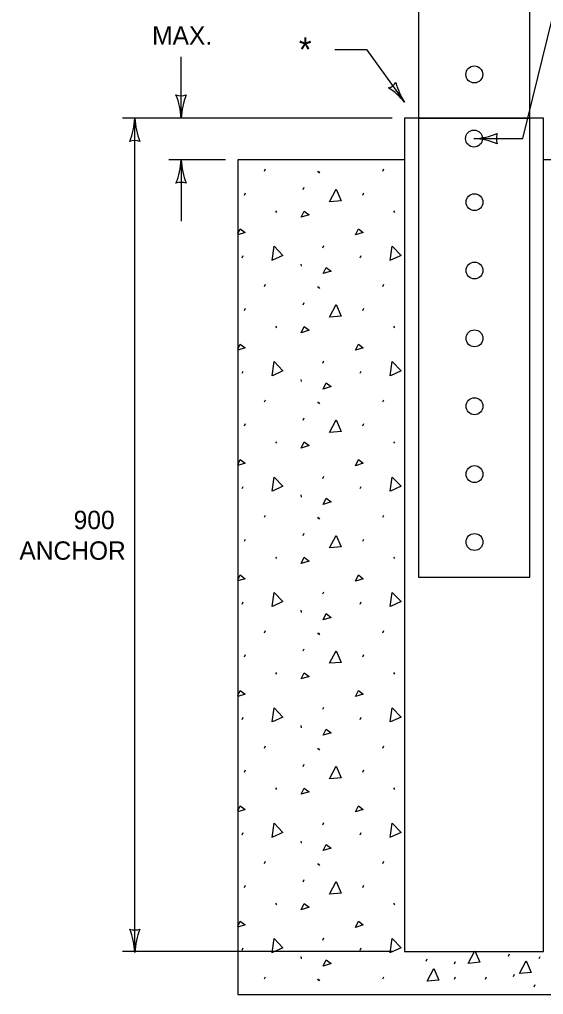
# Model space of a CAD drawing. Extents: x 49940 to 50043, y 49986 to 50011.
# Drawn here: x 50038.243 to 50039.957, y 49990.668 to 49993.853 of the extents above; entities that cross this region are included whole.
import ezdxf

# ---------------------------------------------------------------- set-up
doc = ezdxf.new("R2010")
doc.units = 0
for name, color, linetype in [('Level 1', 7, 'Continuous'), ('Level 2', 7, 'Continuous'), ('Level 3', 7, 'Continuous'), ('Level 4', 7, 'Continuous')]:
    doc.layers.add(name, color=color, linetype=linetype)

msp = doc.modelspace()

# ---------------------------------------------------------------- linework, layer by layer
at = {"layer": 'Level 1'}
for p, q in [((50039.9566, 49993.5307), (50039.5022, 49993.5307)), ((50039.5022, 49993.5307), (50039.5022, 49990.8091)), ((50039.9566, 49990.8091), (50039.9566, 49993.5307)), ((50039.5022, 49993.3944), (50038.9568, 49993.3944)), ((50038.9568, 49993.3944), (50038.9568, 49990.6682)), ((50040.5018, 49993.3944), (50039.9566, 49993.3944)), ((50039.0446, 49993.358), (50039.0478, 49993.3652)), ((50039.2181, 49993.358), (50039.2214, 49993.353)), ((50039.2214, 49993.3561), (50039.2247, 49993.3513)), ((50039.4311, 49993.358), (50039.4344, 49993.3652)), ((50038.9792, 49993.2795), (50038.9823, 49993.2868)), ((50039.1704, 49993.2981), (50039.1736, 49993.3054)), ((50039.3658, 49993.2795), (50039.369, 49993.2868)), ((50039.08, 49993.228), (50039.0833, 49993.2231)), ((50039.4666, 49993.228), (50039.4698, 49993.2231)), ((50039.235, 49993.1076), (50039.2383, 49993.115)), ((50038.9712, 49993.0745), (50038.9744, 49993.0819)), ((50039.3577, 49993.0745), (50039.3608, 49993.0819)), ((50039.163, 49993.0543), (50039.1638, 49993.0469)), ((50039.0446, 49992.981), (50039.0478, 49992.9883)), ((50039.2181, 49992.981), (50039.2214, 49992.9761)), ((50039.2214, 49992.979), (50039.2247, 49992.9743)), ((50039.4311, 49992.981), (50039.4344, 49992.9883)), ((50038.9792, 49992.9027), (50038.9823, 49992.9099)), ((50039.1704, 49992.9212), (50039.1736, 49992.9285)), ((50039.3658, 49992.9027), (50039.369, 49992.9099)), ((50039.08, 49992.851), (50039.0833, 49992.8461)), ((50039.4666, 49992.851), (50039.4698, 49992.8461)), ((50039.235, 49992.7307), (50039.2383, 49992.738)), ((50038.9712, 49992.6976), (50038.9744, 49992.7048)), ((50039.163, 49992.6774), (50039.1638, 49992.6701)), ((50039.3577, 49992.6976), (50039.3608, 49992.7048)), ((50039.0446, 49992.604), (50039.0478, 49992.6112)), ((50039.4311, 49992.604), (50039.4344, 49992.6112)), ((50039.2181, 49992.604), (50039.2214, 49992.5993)), ((50039.2214, 49992.6022), (50039.2247, 49992.5973)), ((50039.1704, 49992.5442), (50039.1736, 49992.5515)), ((50038.9792, 49992.5257), (50038.9823, 49992.5329)), ((50039.3658, 49992.5257), (50039.369, 49992.5329)), ((50039.08, 49992.474), (50039.0833, 49992.469)), ((50039.4666, 49992.474), (50039.4698, 49992.469)), ((50039.235, 49992.3538), (50039.2383, 49992.361)), ((50038.9712, 49992.3206), (50038.9744, 49992.3279)), ((50039.3577, 49992.3206), (50039.3608, 49992.3279)), ((50039.163, 49992.3003), (50039.1638, 49992.2932)), ((50039.0446, 49992.2271), (50039.0478, 49992.2343)), ((50039.4311, 49992.2271), (50039.4344, 49992.2343)), ((50039.2181, 49992.2271), (50039.2214, 49992.2223)), ((50039.2214, 49992.2252), (50039.2247, 49992.2204)), ((50039.1704, 49992.1672), (50039.1736, 49992.1746)), ((50038.9792, 49992.1487), (50038.9823, 49992.1559)), ((50039.3658, 49992.1487), (50039.369, 49992.1559)), ((50039.08, 49992.0971), (50039.0833, 49992.0921)), ((50039.4666, 49992.0971), (50039.4698, 49992.0921)), ((50039.235, 49991.9767), (50039.2383, 49991.984)), ((50038.9712, 49991.9437), (50038.9744, 49991.9509)), ((50039.3577, 49991.9437), (50039.3608, 49991.9509)), ((50039.163, 49991.9233), (50039.1638, 49991.9162)), ((50039.0446, 49991.85), (50039.0478, 49991.8573)), ((50039.2181, 49991.85), (50039.2214, 49991.8452)), ((50039.2214, 49991.8482), (50039.2247, 49991.8434)), ((50039.4311, 49991.85), (50039.4344, 49991.8573)), ((50039.1704, 49991.7903), (50039.1736, 49991.7976)), ((50038.9792, 49991.7717), (50038.9823, 49991.779)), ((50039.3658, 49991.7717), (50039.369, 49991.779)), ((50039.08, 49991.72), (50039.0833, 49991.7151)), ((50039.4666, 49991.72), (50039.4698, 49991.7151)), ((50039.235, 49991.5998), (50039.2383, 49991.607)), ((50038.9712, 49991.5668), (50038.9744, 49991.574)), ((50039.3577, 49991.5668), (50039.3608, 49991.574)), ((50039.163, 49991.5466), (50039.1638, 49991.5392)), ((50039.0446, 49991.4731), (50039.0478, 49991.4804)), ((50039.2181, 49991.4731), (50039.2214, 49991.4683)), ((50039.2214, 49991.4712), (50039.2247, 49991.4664)), ((50039.4311, 49991.4731), (50039.4344, 49991.4804)), ((50038.9792, 49991.3947), (50038.9823, 49991.4019)), ((50039.1704, 49991.4133), (50039.1736, 49991.4206)), ((50039.3658, 49991.3947), (50039.369, 49991.4019)), ((50039.08, 49991.3431), (50039.0833, 49991.3383)), ((50039.4666, 49991.3431), (50039.4698, 49991.3383)), ((50039.235, 49991.2229), (50039.2383, 49991.2301)), ((50038.9712, 49991.1897), (50038.9744, 49991.1969)), ((50039.3577, 49991.1897), (50039.3608, 49991.1969)), ((50039.163, 49991.1694), (50039.1638, 49991.1622)), ((50039.0446, 49991.0961), (50039.0478, 49991.1034)), ((50039.2181, 49991.0961), (50039.2214, 49991.0913)), ((50039.2214, 49991.0943), (50039.2247, 49991.0894)), ((50039.4311, 49991.0961), (50039.4344, 49991.1034)), ((50038.9792, 49991.0177), (50038.9823, 49991.0251)), ((50039.1704, 49991.0362), (50039.1736, 49991.0437)), ((50039.3658, 49991.0177), (50039.369, 49991.0251)), ((50039.08, 49990.9661), (50039.0833, 49990.9613)), ((50039.4666, 49990.9661), (50039.4698, 49990.9613)), ((50039.235, 49990.8458), (50039.2383, 49990.853)), ((50038.9712, 49990.8128), (50038.9744, 49990.8201)), ((50039.3577, 49990.8128), (50039.3608, 49990.8201)), ((50039.5022, 49990.8091), (50039.9566, 49990.8091)), ((50039.8423, 49990.7936), (50039.8456, 49990.8009)), ((50039.163, 49990.7925), (50039.1638, 49990.7852)), ((50039.5735, 49990.777), (50039.5768, 49990.7842)), ((50039.666, 49990.7687), (50039.6692, 49990.7759)), ((50039.9431, 49990.7853), (50039.9463, 49990.7926)), ((50039.8591, 49990.7266), (50039.8623, 49990.7341)), ((50039.0446, 49990.7191), (50039.0478, 49990.7264)), ((50039.2181, 49990.7191), (50039.2214, 49990.7143)), ((50039.2214, 49990.7174), (50039.2247, 49990.7125)), ((50039.4311, 49990.7191), (50039.4344, 49990.7264)), ((50039.666, 49990.7183), (50039.6692, 49990.7257)), ((50039.7668, 49990.7183), (50039.7699, 49990.7257)), ((50039.9262, 49990.6934), (50039.9296, 49990.7006)), ((50038.9568, 49990.6682), (50040.5018, 49990.6682))]:
    msp.add_line(p, q, dxfattribs=at)
for points in [[(50039.5482, 49994.4155), (50039.5482, 49993.5309), (50039.9116, 49993.5309), (50039.9114, 49994.4156)], [(50039.2568, 49993.2578), (50039.2786, 49993.2989), (50039.2955, 49993.261), (50039.2576, 49993.2578)], [(50039.1648, 49993.207), (50039.1746, 49993.2271), (50039.1908, 49993.2151), (50039.1648, 49993.207)], [(50038.9568, 49993.1528), (50038.9649, 49993.1694), (50038.981, 49993.1574), (50038.9568, 49993.1497)], [(50039.3419, 49993.1492), (50039.3515, 49993.1694), (50039.3675, 49993.1574), (50039.3419, 49993.1492)], [(50039.0692, 49993.0661), (50039.0757, 49993.1123), (50039.1046, 49993.0826), (50039.0702, 49993.0666)], [(50039.4559, 49993.0661), (50039.4624, 49993.1123), (50039.4913, 49993.0826), (50039.4567, 49993.0666)], [(50039.2366, 49993.0228), (50039.2464, 49993.0432), (50039.2626, 49993.031), (50039.2366, 49993.0228)], [(50039.2568, 49992.8808), (50039.2786, 49992.9219), (50039.2955, 49992.884), (50039.2576, 49992.8808)], [(50039.1648, 49992.83), (50039.1746, 49992.85), (50039.1908, 49992.8381), (50039.1648, 49992.83)], [(50038.9568, 49992.7758), (50038.9649, 49992.7925), (50038.981, 49992.7804), (50038.9568, 49992.7728)], [(50039.3419, 49992.7724), (50039.3515, 49992.7925), (50039.3675, 49992.7804), (50039.3419, 49992.7724)], [(50039.0692, 49992.6893), (50039.0757, 49992.7354), (50039.1046, 49992.7056), (50039.0702, 49992.6896)], [(50039.4559, 49992.6893), (50039.4624, 49992.7354), (50039.4913, 49992.7056), (50039.4567, 49992.6896)], [(50039.2366, 49992.646), (50039.2464, 49992.6661), (50039.2626, 49992.6541), (50039.2366, 49992.646)], [(50039.2568, 49992.5038), (50039.2786, 49992.545), (50039.2955, 49992.5071), (50039.2576, 49992.5038)], [(50039.1648, 49992.4529), (50039.1746, 49992.4732), (50039.1908, 49992.4611), (50039.1648, 49992.4529)], [(50038.9568, 49992.3987), (50038.9649, 49992.4155), (50038.981, 49992.4034), (50038.9568, 49992.3957)], [(50039.3419, 49992.3952), (50039.3515, 49992.4155), (50039.3675, 49992.4034), (50039.3419, 49992.3952)], [(50039.0692, 49992.3124), (50039.0757, 49992.3584), (50039.1046, 49992.3286), (50039.0702, 49992.3125)], [(50039.4559, 49992.3124), (50039.4624, 49992.3584), (50039.4913, 49992.3286), (50039.4567, 49992.3125)], [(50039.2366, 49992.269), (50039.2464, 49992.2891), (50039.2626, 49992.2772), (50039.2366, 49992.269)], [(50039.2568, 49992.127), (50039.2786, 49992.168), (50039.2955, 49992.1302), (50039.2576, 49992.127)], [(50039.1648, 49992.076), (50039.1746, 49992.0963), (50039.1908, 49992.084), (50039.1648, 49992.076)], [(50038.9568, 49992.0218), (50038.9649, 49992.0385), (50038.981, 49992.0264), (50038.9568, 49992.019)], [(50039.3419, 49992.0183), (50039.3515, 49992.0385), (50039.3675, 49992.0264), (50039.3419, 49992.0183)], [(50039.0692, 49991.9353), (50039.0757, 49991.9815), (50039.1046, 49991.9517), (50039.0702, 49991.9356)], [(50039.4559, 49991.9353), (50039.4624, 49991.9815), (50039.4913, 49991.9517), (50039.4567, 49991.9356)], [(50039.2366, 49991.8921), (50039.2464, 49991.9122), (50039.2626, 49991.9001), (50039.2366, 49991.8921)], [(50039.2568, 49991.75), (50039.2786, 49991.791), (50039.2955, 49991.7532), (50039.2576, 49991.75)], [(50039.1648, 49991.6991), (50039.1746, 49991.7193), (50039.1908, 49991.7071), (50039.1648, 49991.6991)], [(50038.9568, 49991.6448), (50038.9649, 49991.6616), (50038.981, 49991.6495), (50038.9568, 49991.642)], [(50039.3419, 49991.6414), (50039.3515, 49991.6616), (50039.3675, 49991.6495), (50039.3419, 49991.6414)], [(50039.0692, 49991.5584), (50039.0757, 49991.6046), (50039.1046, 49991.5746), (50039.0702, 49991.5587)], [(50039.4559, 49991.5584), (50039.4624, 49991.6046), (50039.4913, 49991.5746), (50039.4567, 49991.5587)], [(50039.2366, 49991.515), (50039.2464, 49991.5352), (50039.2626, 49991.5231), (50039.2366, 49991.515)], [(50039.2568, 49991.3728), (50039.2786, 49991.4141), (50039.2955, 49991.3761), (50039.2576, 49991.3728)], [(50039.1648, 49991.3221), (50039.1746, 49991.3422), (50039.1908, 49991.3302), (50039.1648, 49991.3221)], [(50038.9568, 49991.2679), (50038.9649, 49991.2846), (50038.981, 49991.2724), (50038.9568, 49991.2648)], [(50039.3419, 49991.2644), (50039.3515, 49991.2846), (50039.3675, 49991.2724), (50039.3419, 49991.2644)], [(50039.0692, 49991.1813), (50039.0757, 49991.2274), (50039.1046, 49991.1976), (50039.0702, 49991.1817)], [(50039.4559, 49991.1813), (50039.4624, 49991.2274), (50039.4913, 49991.1976), (50039.4567, 49991.1817)], [(50039.2366, 49991.1381), (50039.2464, 49991.1583), (50039.2626, 49991.1462), (50039.2366, 49991.1381)], [(50039.2568, 49990.996), (50039.2786, 49991.0372), (50039.2955, 49990.9993), (50039.2576, 49990.996)], [(50039.1648, 49990.9452), (50039.1746, 49990.9652), (50039.1908, 49990.9532), (50039.1648, 49990.9452)], [(50038.9568, 49990.8908), (50038.9649, 49990.9076), (50038.981, 49990.8956), (50038.9568, 49990.888)], [(50039.3419, 49990.8874), (50039.3515, 49990.9076), (50039.3675, 49990.8956), (50039.3419, 49990.8874)], [(50039.0692, 49990.8043), (50039.0757, 49990.8506), (50039.1046, 49990.8207), (50039.0702, 49990.8049)], [(50039.4559, 49990.8043), (50039.4624, 49990.8506), (50039.4913, 49990.8207), (50039.4567, 49990.8049)], [(50039.7104, 49990.77), (50039.732, 49990.8112), (50039.749, 49990.7733), (50039.7111, 49990.77)], [(50039.2366, 49990.7612), (50039.2464, 49990.7812), (50039.2626, 49990.7691), (50039.2366, 49990.7612)], [(50039.8783, 49990.7366), (50039.9, 49990.7778), (50039.917, 49990.7399), (50039.8791, 49990.7366)], [(50039.5759, 49990.7114), (50039.5977, 49990.7526), (50039.6147, 49990.7147), (50039.5767, 49990.7114)]]:
    msp.add_lwpolyline(points, dxfattribs=at)
for centre in [(50039.7305, 49993.6737), (50039.7295, 49993.4639), (50039.7311, 49993.2563), (50039.7311, 49993.0332), (50039.7311, 49992.8115), (50039.7311, 49992.5898), (50039.7311, 49992.3681), (50039.7311, 49992.1463)]:
    msp.add_circle(centre, 0.0277, dxfattribs=at)
at = {"layer": 'Level 3'}
for p, q in [((50039.8897, 49993.4639), (50040.1695, 49994.6075)), ((50038.7718, 49993.5307), (50038.7718, 49993.7307)), ((50039.2747, 49993.7547), (50039.378, 49993.7547)), ((50039.378, 49993.7547), (50039.5022, 49993.5829)), ((50039.4622, 49993.5307), (50038.5803, 49993.5307)), ((50038.6203, 49990.8058), (50038.6203, 49993.5307)), ((50039.7295, 49993.4639), (50039.8897, 49993.4639)), ((50038.9168, 49993.3944), (50038.7318, 49993.3944)), ((50038.7718, 49993.3944), (50038.7718, 49993.1944)), ((50039.4622, 49990.8091), (50038.5803, 49990.8091))]:
    msp.add_line(p, q, dxfattribs=at)
for centre, radius, start, end in [((50039.4347, 49993.6764), 0.0493, 288.0017, 323.724), ((50039.3386, 49993.4518), 0.2097, 38.6902, 57.94), ((50039.6691, 49993.6933), 0.2001, 193.3189, 213.5024), ((50038.7718, 49993.6589), 0.0548, 252.1388, 287.8612), ((50038.5391, 49993.5192), 0.233, 2.8273, 22.0772), ((50038.994, 49993.5215), 0.2223, 157.456, 177.6395), ((50038.3982, 49993.5399), 0.2223, 337.456, 357.6395), ((50038.853, 49993.5422), 0.233, 182.8273, 202.0772), ((50039.718, 49993.6966), 0.233, 272.8273, 292.0772), ((50039.8577, 49993.4639), 0.0548, 162.1388, 197.8612), ((50038.6203, 49993.4025), 0.0548, 72.1388, 107.8612), ((50039.7204, 49993.2418), 0.2223, 67.456, 87.6395), ((50038.5497, 49993.4036), 0.2223, 337.456, 357.6395), ((50039.0045, 49993.4059), 0.233, 182.8273, 202.0772), ((50038.7718, 49993.2662), 0.0548, 72.1388, 107.8612), ((50038.6203, 49990.934), 0.0548, 252.1388, 287.8612), ((50038.3876, 49990.7943), 0.233, 2.8273, 22.0772), ((50038.8425, 49990.7966), 0.2223, 157.456, 177.6395)]:
    msp.add_arc(centre, radius, start, end, dxfattribs=at)
at = {"layer": 'Level 4'}
for p, q in [((50039.5482, 49993.5309), (50039.5482, 49992.0313)), ((50039.9116, 49992.0313), (50039.9116, 49993.5309)), ((50039.5482, 49992.0313), (50039.9116, 49992.0313))]:
    msp.add_line(p, q, dxfattribs=at)

# ---------------------------------------------------------------- texts
at = {"layer": 'Level 2'}
for s, p in [('MAX.', (50038.677, 49993.7707)), ('900', (50038.4204, 49992.1883)), ('ANCHOR', (50038.243, 49992.0883))]:
    msp.add_text(s, height=0.06, dxfattribs=at).set_placement(p)
msp.add_text('*', height=0.08, rotation=359.5, dxfattribs=at).set_placement((50039.1563, 49993.7154))

doc.saveas('drawing.dxf')
